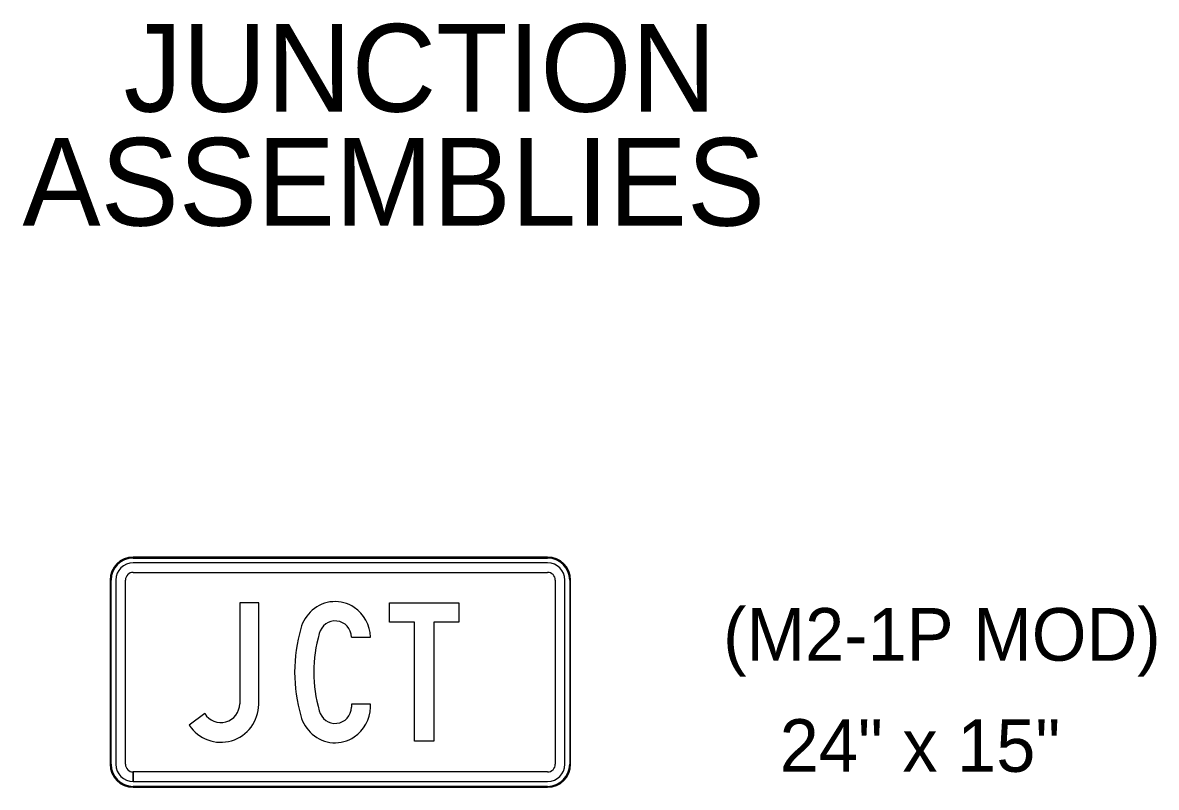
# Model space of a CAD drawing. Extents: x 17890587 to 17890754, y 17897693 to 17897992.
# Drawn here: x 17890603.57 to 17890607.934, y 17897885.813 to 17897888.756 of the extents above; entities that cross this region are included whole.
import ezdxf

# ---------------------------------------------------------------- set-up
doc = ezdxf.new("R2010")
doc.units = 0
doc.layers.add('GSColorFill', color=7, linetype='Continuous')
doc.layers.add('TextMisc', color=7, linetype='Continuous')

msp = doc.modelspace()

# ---------------------------------------------------------------- linework, layer by layer
at = {"layer": 'GSColorFill'}
for p, q in [((17890605.5909, 17897886.6994), (17890603.9954, 17897886.6994)), ((17890605.5909, 17897886.6994), (17890603.9954, 17897886.6994)), ((17890603.9954, 17897886.6957), (17890605.5909, 17897886.6957)), ((17890605.5909, 17897886.6772), (17890603.9954, 17897886.6772)), ((17890603.9954, 17897886.6403), (17890605.5909, 17897886.6403)), ((17890603.9068, 17897886.6108), (17890603.9068, 17897885.9016)), ((17890603.9068, 17897886.6108), (17890603.9068, 17897885.9016)), ((17890603.9105, 17897885.9016), (17890603.9105, 17897886.6108)), ((17890603.9289, 17897886.6108), (17890603.9289, 17897885.9016)), ((17890603.9659, 17897885.9016), (17890603.9659, 17897886.6108)), ((17890605.6204, 17897886.6108), (17890605.6204, 17897885.9016)), ((17890605.6574, 17897885.9016), (17890605.6574, 17897886.6108)), ((17890605.6758, 17897886.6108), (17890605.6758, 17897885.9016)), ((17890605.6795, 17897885.9016), (17890605.6795, 17897886.6108)), ((17890605.6795, 17897885.9016), (17890605.6795, 17897886.6108)), ((17890604.8357, 17897886.3913), (17890604.909, 17897886.3913)), ((17890604.8357, 17897886.3913), (17890604.909, 17897886.3913)), ((17890604.8357, 17897886.3913), (17890604.909, 17897886.3913)), ((17890604.909, 17897886.1211), (17890604.909, 17897886.1329)), ((17890604.909, 17897886.1211), (17890604.909, 17897886.1329)), ((17890604.909, 17897886.1211), (17890604.909, 17897886.1329)), ((17890604.271, 17897886.0969), (17890604.2113, 17897886.0523)), ((17890604.271, 17897886.0969), (17890604.2113, 17897886.0523)), ((17890604.271, 17897886.0969), (17890604.2113, 17897886.0523)), ((17890604.271, 17897886.0969), (17890604.271, 17897886.0969)), ((17890604.271, 17897886.0969), (17890604.271, 17897886.0969)), ((17890604.271, 17897886.0969), (17890604.271, 17897886.0969)), ((17890603.9954, 17897885.8352), (17890603.9954, 17897885.8721)), ((17890605.5909, 17897885.8721), (17890603.9958, 17897885.8721)), ((17890603.9958, 17897885.8721), (17890603.9958, 17897885.8352)), ((17890603.9954, 17897885.813), (17890603.9954, 17897885.8167)), ((17890605.5909, 17897885.8167), (17890603.9954, 17897885.8167)), ((17890603.9954, 17897885.8167), (17890603.9954, 17897885.813)), ((17890603.9954, 17897885.813), (17890605.5909, 17897885.813)), ((17890603.9954, 17897885.813), (17890605.5909, 17897885.813)), ((17890603.9958, 17897885.8352), (17890605.5909, 17897885.8352))]:
    msp.add_line(p, q, dxfattribs=at)
for points in [[(17890604.4791, 17897886.1322), (17890604.4791, 17897886.5226), (17890604.4057, 17897886.5226), (17890604.4057, 17897886.1347)], [(17890604.4791, 17897886.1322), (17890604.4791, 17897886.5226), (17890604.4057, 17897886.5226), (17890604.4057, 17897886.1347)], [(17890604.4791, 17897886.1322), (17890604.4791, 17897886.5226), (17890604.4057, 17897886.5226), (17890604.4057, 17897886.1347)], [(17890604.909, 17897886.1329), (17890604.8357, 17897886.1329), (17890604.8357, 17897886.1211)], [(17890604.909, 17897886.1329), (17890604.8357, 17897886.1329), (17890604.8357, 17897886.1211)], [(17890604.909, 17897886.1329), (17890604.8357, 17897886.1329), (17890604.8357, 17897886.1211)]]:
    msp.add_lwpolyline(points, dxfattribs=at)
msp.add_lwpolyline([(17890605.0788, 17897886.4481), (17890604.9819, 17897886.4481), (17890604.9819, 17897886.5226), (17890605.2491, 17897886.5226), (17890605.2491, 17897886.4481), (17890605.1522, 17897886.4481), (17890605.1522, 17897885.9907), (17890605.0788, 17897885.9907)], close=True, dxfattribs=at)
msp.add_lwpolyline([(17890605.0788, 17897886.4481), (17890604.9819, 17897886.4481), (17890604.9819, 17897886.5226), (17890605.2491, 17897886.5226), (17890605.2491, 17897886.4481), (17890605.1522, 17897886.4481), (17890605.1522, 17897885.9907), (17890605.0788, 17897885.9907)], close=True, dxfattribs=at)
msp.add_lwpolyline([(17890605.0788, 17897886.4481), (17890604.9819, 17897886.4481), (17890604.9819, 17897886.5226), (17890605.2491, 17897886.5226), (17890605.2491, 17897886.4481), (17890605.1522, 17897886.4481), (17890605.1522, 17897885.9907), (17890605.0788, 17897885.9907)], close=True, dxfattribs=at)
for centre, radius, start, end in [((17890603.9954, 17897886.6108), 0.0886, 90, 180), ((17890603.9954, 17897886.6108), 0.0886, 90, 180), ((17890603.9954, 17897886.6108), 0.0849, 90, 180), ((17890605.5909, 17897886.6108), 0.0886, 0, 90), ((17890605.5909, 17897886.6108), 0.0886, 0, 90), ((17890605.5909, 17897886.6108), 0.0849, 0, 90), ((17890603.9954, 17897886.6108), 0.0665, 90, 180), ((17890603.9954, 17897886.6108), 0.0295, 90, 180), ((17890605.5909, 17897886.6108), 0.0665, 0, 90), ((17890605.5909, 17897886.6108), 0.0295, 0, 90), ((17890603.9954, 17897885.9016), 0.0886, 180, 270), ((17890603.9954, 17897885.9016), 0.0886, 180, 270), ((17890603.9954, 17897885.9016), 0.0849, 180, 270), ((17890603.9954, 17897885.9016), 0.0665, 180, 270), ((17890603.9954, 17897885.9016), 0.0295, 180, 270), ((17890605.5909, 17897885.9016), 0.0886, 270, 0), ((17890605.5909, 17897885.9016), 0.0886, 270, 0), ((17890605.5909, 17897885.9016), 0.0849, 270, 0), ((17890605.5909, 17897885.9016), 0.0665, 270, 0), ((17890605.5909, 17897885.9016), 0.0295, 270, 0)]:
    msp.add_arc(centre, radius, start, end, dxfattribs=at)
for centre, major_axis, start_param, end_param in [((17890604.7725, 17897886.3915), (0, 0.1364), 5.699182, 6.997659), ((17890604.7725, 17897886.3915), (0, 0.1364), 5.699182, 6.997659), ((17890604.7725, 17897886.3915), (0, 0.1364), 5.699182, 6.997659), ((17890604.7847, 17897886.3803), (0, 0.153), 0.727812, 1.2769), ((17890604.7847, 17897886.3803), (0, 0.153), 0.727812, 1.2769), ((17890604.7847, 17897886.3803), (0, 0.153), 0.727812, 1.2769), ((17890604.7685, 17897886.3866), (0, 0.1427), 4.74507, 5.694085), ((17890604.7685, 17897886.3866), (0, 0.1427), 4.74507, 5.694085), ((17890604.7685, 17897886.3866), (0, 0.1427), 4.74507, 5.694085), ((17890605.2792, 17897886.2472), (0, 0.6723), 1.303737, 1.557401), ((17890605.2792, 17897886.2472), (0, 0.6723), 1.303737, 1.557401), ((17890605.2792, 17897886.2472), (0, 0.6723), 1.303737, 1.557401), ((17890604.773, 17897886.3897), (0, 0.0637), 4.736859, 7.616752), ((17890604.773, 17897886.3897), (0, 0.0637), 4.736859, 7.616752), ((17890604.773, 17897886.3897), (0, 0.0637), 4.736859, 7.616752), ((17890605.2202, 17897886.2539), (0, 0.5376), 1.286527, 1.566552), ((17890605.2202, 17897886.2539), (0, 0.5376), 1.286527, 1.566552), ((17890605.2202, 17897886.2539), (0, 0.5376), 1.286527, 1.566552), ((17890605.2792, 17897886.2652), (0, 0.6723), 1.584191, 1.837856), ((17890605.2792, 17897886.2652), (0, 0.6723), 1.584191, 1.837856), ((17890605.2792, 17897886.2652), (0, 0.6723), 1.584191, 1.837856), ((17890605.2202, 17897886.2585), (0, 0.5376), 1.575041, 1.855066), ((17890605.2202, 17897886.2585), (0, 0.5376), 1.575041, 1.855066), ((17890605.2202, 17897886.2585), (0, 0.5376), 1.575041, 1.855066), ((17890604.3328, 17897886.1349), (0, 0.1485), 2.160989, 4.69444), ((17890604.3328, 17897886.1349), (0, 0.1485), 2.160989, 4.69444), ((17890604.3328, 17897886.1349), (0, 0.1485), 2.160989, 4.69444), ((17890604.3328, 17897886.1362), (0, 0.074), 2.129975, 4.692037), ((17890604.3328, 17897886.1362), (0, 0.074), 2.129975, 4.692037), ((17890604.3328, 17897886.1362), (0, 0.074), 2.129975, 4.692037), ((17890604.773, 17897886.1227), (0, 0.0637), 1.808026, 4.687919), ((17890604.773, 17897886.1227), (0, 0.0637), 1.808026, 4.687919), ((17890604.773, 17897886.1227), (0, 0.0637), 1.808026, 4.687919), ((17890604.7685, 17897886.1258), (0, 0.1427), 3.730693, 4.679708), ((17890604.7685, 17897886.1258), (0, 0.1427), 3.730693, 4.679708), ((17890604.7685, 17897886.1258), (0, 0.1427), 3.730693, 4.679708), ((17890604.7847, 17897886.1321), (0, 0.153), 1.864693, 2.41378), ((17890604.7847, 17897886.1321), (0, 0.153), 1.864693, 2.41378), ((17890604.7847, 17897886.1321), (0, 0.153), 1.864693, 2.41378), ((17890604.7725, 17897886.1209), (0, 0.1364), 2.427119, 3.725595), ((17890604.7725, 17897886.1209), (0, 0.1364), 2.427119, 3.725595), ((17890604.7725, 17897886.1209), (0, 0.1364), 2.427119, 3.725595)]:
    msp.add_ellipse(centre, major_axis=major_axis, ratio=0.985, start_param=start_param, end_param=end_param, dxfattribs=at)

# ---------------------------------------------------------------- texts
at = {"layer": 'TextMisc'}
for s, height, p in [('JUNCTION', 0.33745, (17890603.9586, 17897888.4137)), ('ASSEMBLIES', 0.33745, (17890603.5691, 17897887.975)), ('(M2-1P MOD)', 0.202479, (17890606.2662, 17897886.3005)), ('24" x 15"', 0.20248, (17890606.4842, 17897885.8727))]:
    msp.add_text(s, height=height, dxfattribs=at).set_placement(p)

doc.saveas('drawing.dxf')
